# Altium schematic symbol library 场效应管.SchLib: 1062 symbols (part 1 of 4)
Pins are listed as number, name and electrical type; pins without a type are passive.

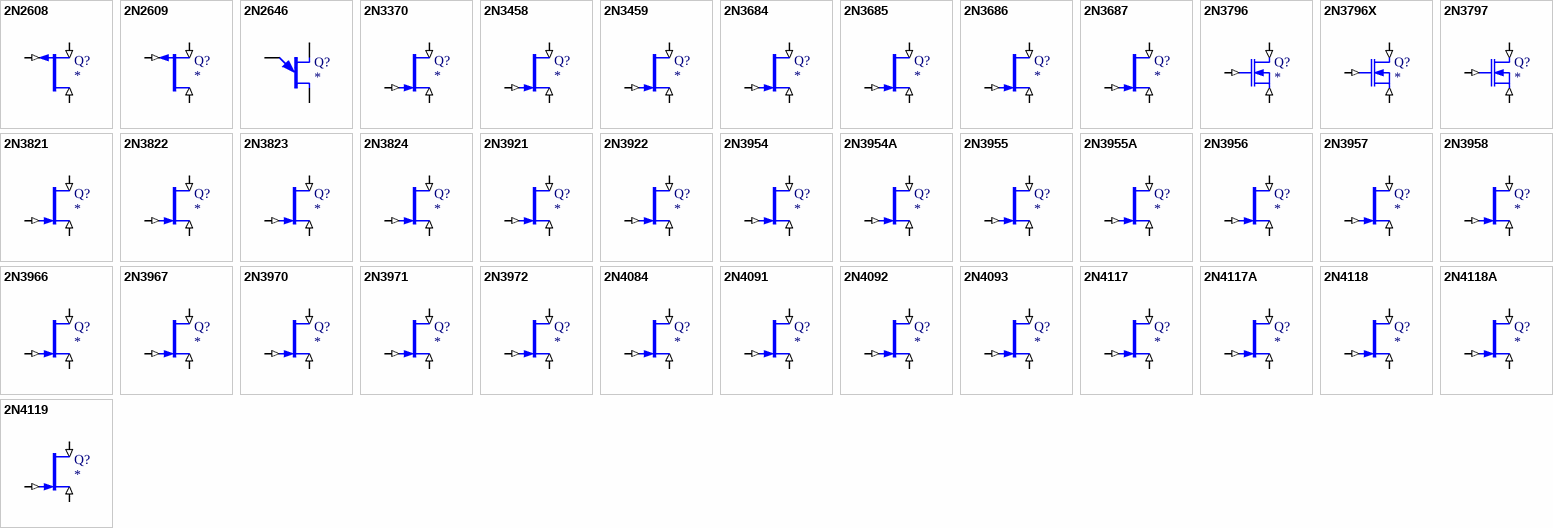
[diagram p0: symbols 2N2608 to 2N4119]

## 2N2608
designator Q?
P-Channel JFET
simulation model 2N2608 (PJFET)
pins: 1 D (in), 2 G (in), 3 S (in)
1 alternate drawing of the same symbol

## 2N2609
designator Q?
P-Channel JFET
simulation model 2N2609 (PJFET)
pins: 1 D (in), 2 G (in), 3 S (in)
1 alternate drawing of the same symbol

## 2N2646
designator Q?
Unijunction Transistor
simulation model 2N2646 (SUBCKT)
pins: 1 B2, 2 E, 3 B1
1 alternate drawing of the same symbol

## 2N3370
designator Q?
N-Channel JFET
simulation model 2N3370 (NJFET)
pins: 1 D (in), 2 G (in), 3 S (in)
1 alternate drawing of the same symbol

## 2N3458
designator Q?
N-Channel JFET
simulation model 2N3458 (NJFET)
pins: 1 D (in), 2 G (in), 3 S (in)
1 alternate drawing of the same symbol

## 2N3459
designator Q?
N-Channel JFET
simulation model 2N3459 (NJFET)
pins: 1 D (in), 2 G (in), 3 S (in)
1 alternate drawing of the same symbol

## 2N3684
designator Q?
N-Channel JFET
simulation model 2N3684 (NJFET)
pins: 1 D (in), 2 G (in), 3 S (in)
1 alternate drawing of the same symbol

## 2N3685
designator Q?
N-Channel JFET
simulation model 2N3685 (NJFET)
pins: 1 D (in), 2 G (in), 3 S (in)
1 alternate drawing of the same symbol

## 2N3686
designator Q?
N-Channel JFET
simulation model 2N3686 (NJFET)
pins: 1 D (in), 2 G (in), 3 S (in)
1 alternate drawing of the same symbol

## 2N3687
designator Q?
N-Channel JFET
simulation model 2N3687 (NJFET)
pins: 1 D (in), 2 G (in), 3 S (in)
1 alternate drawing of the same symbol

## 2N3796
designator Q?
N-Channel MOSFET
simulation model 2N3796 (NEMOS)
pins: 1 D (in), 2 G (in), 3 S (in)
1 alternate drawing of the same symbol

## 2N3796X
designator Q?
N-Channel MOSFET
simulation model 2N3796X (NEMOS)
pins: 1 D (in), 2 G (in), 3 S (in)
1 alternate drawing of the same symbol

## 2N3797
designator Q?
N-Channel MOSFET
simulation model 2N3797 (NEMOS)
pins: 1 D (in), 2 G (in), 3 S (in)
1 alternate drawing of the same symbol

## 2N3821
designator Q?
N-Channel JFET
simulation model 2N3821 (NJFET)
pins: 1 D (in), 2 G (in), 3 S (in)
1 alternate drawing of the same symbol

## 2N3822
designator Q?
N-Channel JFET
simulation model 2N3822 (NJFET)
pins: 1 D (in), 2 G (in), 3 S (in)
1 alternate drawing of the same symbol

## 2N3823
designator Q?
N-Channel JFET
simulation model 2N3823 (NJFET)
pins: 1 D (in), 2 G (in), 3 S (in)
1 alternate drawing of the same symbol

## 2N3824
designator Q?
N-Channel JFET
simulation model 2N3824 (NJFET)
pins: 1 D (in), 2 G (in), 3 S (in)
1 alternate drawing of the same symbol

## 2N3921
designator Q?
N-Channel JFET
simulation model 2N3921 (NJFET)
pins: 1 D (in), 2 G (in), 3 S (in)
1 alternate drawing of the same symbol

## 2N3922
designator Q?
N-Channel JFET
simulation model 2N3922 (NJFET)
pins: 1 D (in), 2 G (in), 3 S (in)
1 alternate drawing of the same symbol

## 2N3954
designator Q?
N-Channel JFET
simulation model 2N3954 (NJFET)
pins: 1 D (in), 2 G (in), 3 S (in)
1 alternate drawing of the same symbol

## 2N3954A
designator Q?
N-Channel JFET
simulation model 2N3954A (NJFET)
pins: 1 D (in), 2 G (in), 3 S (in)
1 alternate drawing of the same symbol

## 2N3955
designator Q?
N-Channel JFET
simulation model 2N3955 (NJFET)
pins: 1 D (in), 2 G (in), 3 S (in)
1 alternate drawing of the same symbol

## 2N3955A
designator Q?
N-Channel JFET
simulation model 2N3955A (NJFET)
pins: 1 D (in), 2 G (in), 3 S (in)
1 alternate drawing of the same symbol

## 2N3956
designator Q?
N-Channel JFET
simulation model 2N3956 (NJFET)
pins: 1 D (in), 2 G (in), 3 S (in)
1 alternate drawing of the same symbol

## 2N3957
designator Q?
N-Channel JFET
simulation model 2N3957 (NJFET)
pins: 1 D (in), 2 G (in), 3 S (in)
1 alternate drawing of the same symbol

## 2N3958
designator Q?
N-Channel JFET
simulation model 2N3958 (NJFET)
pins: 1 D (in), 2 G (in), 3 S (in)
1 alternate drawing of the same symbol

## 2N3966
designator Q?
N-Channel JFET
simulation model 2N3966 (NJFET)
pins: 1 D (in), 2 G (in), 3 S (in)
1 alternate drawing of the same symbol

## 2N3967
designator Q?
N-Channel JFET
simulation model 2N3967 (NJFET)
pins: 1 D (in), 2 G (in), 3 S (in)
1 alternate drawing of the same symbol

## 2N3970
designator Q?
N-Channel JFET
simulation model 2N3970 (NJFET)
pins: 1 D (in), 2 G (in), 3 S (in)
1 alternate drawing of the same symbol

## 2N3971
designator Q?
N-Channel JFET
simulation model 2N3971 (NJFET)
pins: 1 D (in), 2 G (in), 3 S (in)
1 alternate drawing of the same symbol

## 2N3972
designator Q?
N-Channel JFET
simulation model 2N3972 (NJFET)
pins: 1 D (in), 2 G (in), 3 S (in)
1 alternate drawing of the same symbol

## 2N4084
designator Q?
N-Channel JFET
simulation model 2N4084 (NJFET)
pins: 1 D (in), 2 G (in), 3 S (in)
1 alternate drawing of the same symbol

## 2N4091
designator Q?
N-Channel JFET
simulation model 2N4091 (NJFET)
pins: 1 D (in), 2 G (in), 3 S (in)
1 alternate drawing of the same symbol

## 2N4092
designator Q?
N-Channel JFET
simulation model 2N4092 (NJFET)
pins: 1 D (in), 2 G (in), 3 S (in)
1 alternate drawing of the same symbol

## 2N4093
designator Q?
N-Channel JFET
simulation model 2N4093 (NJFET)
pins: 1 D (in), 2 G (in), 3 S (in)
1 alternate drawing of the same symbol

## 2N4117
designator Q?
N-Channel JFET
simulation model 2N4117 (NJFET)
pins: 1 D (in), 2 G (in), 3 S (in)
1 alternate drawing of the same symbol

## 2N4117A
designator Q?
N-Channel JFET
simulation model 2N4117A (NJFET)
pins: 1 D (in), 2 G (in), 3 S (in)
1 alternate drawing of the same symbol

## 2N4118
designator Q?
N-Channel JFET
simulation model 2N4118 (NJFET)
pins: 1 D (in), 2 G (in), 3 S (in)
1 alternate drawing of the same symbol

## 2N4118A
designator Q?
N-Channel JFET
simulation model 2N4118A (NJFET)
pins: 1 D (in), 2 G (in), 3 S (in)
1 alternate drawing of the same symbol

## 2N4119
designator Q?
N-Channel JFET
simulation model 2N4119 (NJFET)
pins: 1 D (in), 2 G (in), 3 S (in)
1 alternate drawing of the same symbol

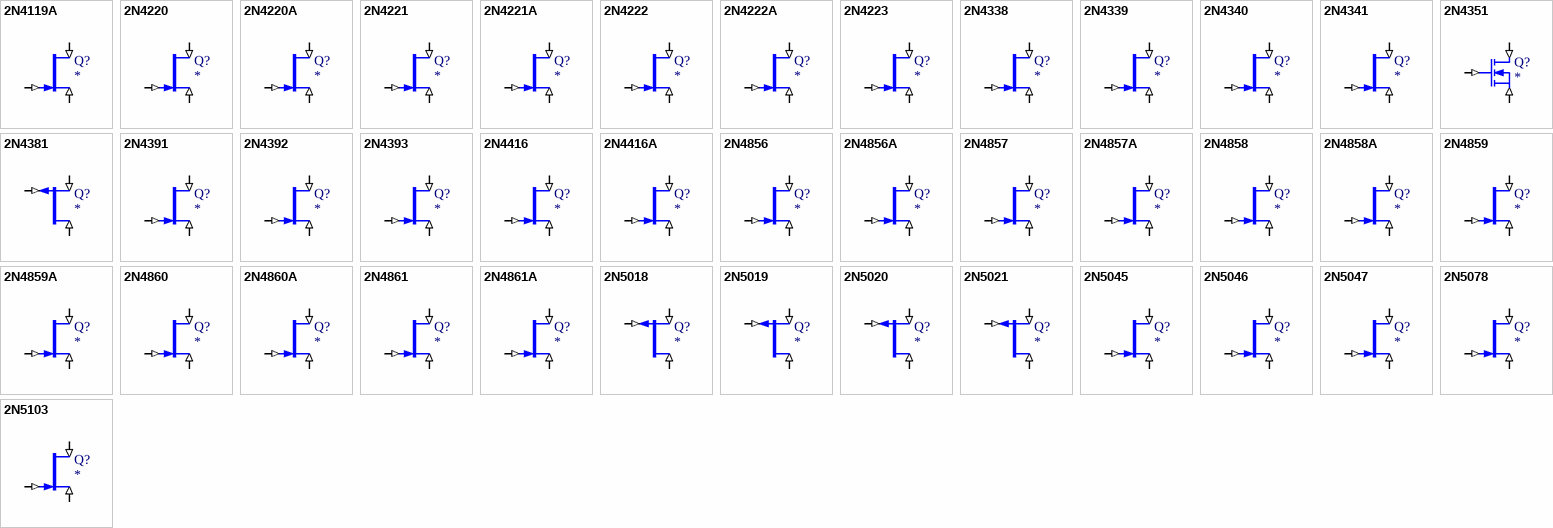
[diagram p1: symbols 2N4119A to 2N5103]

## 2N4119A
designator Q?
N-Channel JFET
simulation model 2N4119A (NJFET)
pins: 1 D (in), 2 G (in), 3 S (in)
1 alternate drawing of the same symbol

## 2N4220
designator Q?
N-Channel JFET
simulation model 2N4220 (NJFET)
pins: 1 D (in), 2 G (in), 3 S (in)
1 alternate drawing of the same symbol

## 2N4220A
designator Q?
N-Channel JFET
simulation model 2N4220A (NJFET)
pins: 1 D (in), 2 G (in), 3 S (in)
1 alternate drawing of the same symbol

## 2N4221
designator Q?
N-Channel JFET
simulation model 2N4221 (NJFET)
pins: 1 D (in), 2 G (in), 3 S (in)
1 alternate drawing of the same symbol

## 2N4221A
designator Q?
N-Channel JFET
simulation model 2N4221A (NJFET)
pins: 1 D (in), 2 G (in), 3 S (in)
1 alternate drawing of the same symbol

## 2N4222
designator Q?
N-Channel JFET
simulation model 2N4222 (NJFET)
pins: 1 D (in), 2 G (in), 3 S (in)
1 alternate drawing of the same symbol

## 2N4222A
designator Q?
N-Channel JFET
simulation model 2N4222A (NJFET)
pins: 1 D (in), 2 G (in), 3 S (in)
1 alternate drawing of the same symbol

## 2N4223
designator Q?
N-Channel JFET
simulation model 2N4223 (NJFET)
pins: 1 D (in), 2 G (in), 3 S (in)
1 alternate drawing of the same symbol

## 2N4338
designator Q?
N-Channel JFET
simulation model 2N4338 (NJFET)
pins: 1 D (in), 2 G (in), 3 S (in)
1 alternate drawing of the same symbol

## 2N4339
designator Q?
N-Channel JFET
simulation model 2N4339 (NJFET)
pins: 1 D (in), 2 G (in), 3 S (in)
1 alternate drawing of the same symbol

## 2N4340
designator Q?
N-Channel JFET
simulation model 2N4340 (NJFET)
pins: 1 D (in), 2 G (in), 3 S (in)
1 alternate drawing of the same symbol

## 2N4341
designator Q?
N-Channel JFET
simulation model 2N4341 (NJFET)
pins: 1 D (in), 2 G (in), 3 S (in)
1 alternate drawing of the same symbol

## 2N4351
designator Q?
N-Channel MOSFET
simulation model 2N4351 (NEMOS)
pins: 1 D (in), 2 G (in), 3 S (in)
1 alternate drawing of the same symbol

## 2N4381
designator Q?
P-Channel JFET
simulation model 2N4381 (PJFET)
pins: 1 D (in), 2 G (in), 3 S (in)
1 alternate drawing of the same symbol

## 2N4391
designator Q?
N-Channel JFET
simulation model 2N4391 (NJFET)
pins: 1 D (in), 2 G (in), 3 S (in)
1 alternate drawing of the same symbol

## 2N4392
designator Q?
N-Channel JFET
simulation model 2N4392 (NJFET)
pins: 1 D (in), 2 G (in), 3 S (in)
1 alternate drawing of the same symbol

## 2N4393
designator Q?
N-Channel JFET
simulation model 2N4393 (NJFET)
pins: 1 D (in), 2 G (in), 3 S (in)
1 alternate drawing of the same symbol

## 2N4416
designator Q?
N-Channel JFET
simulation model 2N4416 (NJFET)
pins: 1 D (in), 2 G (in), 3 S (in)
1 alternate drawing of the same symbol

## 2N4416A
designator Q?
N-Channel JFET
simulation model 2N4416A (NJFET)
pins: 1 D (in), 2 G (in), 3 S (in)
1 alternate drawing of the same symbol

## 2N4856
designator Q?
N-Channel JFET
simulation model 2N4856 (NJFET)
pins: 1 D (in), 2 G (in), 3 S (in)
1 alternate drawing of the same symbol

## 2N4856A
designator Q?
N-Channel JFET
simulation model 2N4856A (NJFET)
pins: 1 D (in), 2 G (in), 3 S (in)
1 alternate drawing of the same symbol

## 2N4857
designator Q?
N-Channel JFET
simulation model 2N4857 (NJFET)
pins: 1 D (in), 2 G (in), 3 S (in)
1 alternate drawing of the same symbol

## 2N4857A
designator Q?
N-Channel JFET
simulation model 2N4857A (NJFET)
pins: 1 D (in), 2 G (in), 3 S (in)
1 alternate drawing of the same symbol

## 2N4858
designator Q?
N-Channel JFET
simulation model 2N4858 (NJFET)
pins: 1 D (in), 2 G (in), 3 S (in)
1 alternate drawing of the same symbol

## 2N4858A
designator Q?
N-Channel JFET
simulation model 2N4858A (NJFET)
pins: 1 D (in), 2 G (in), 3 S (in)
1 alternate drawing of the same symbol

## 2N4859
designator Q?
N-Channel JFET
simulation model 2N4859 (NJFET)
pins: 1 D (in), 2 G (in), 3 S (in)
1 alternate drawing of the same symbol

## 2N4859A
designator Q?
N-Channel JFET
simulation model 2N4859A (NJFET)
pins: 1 D (in), 2 G (in), 3 S (in)
1 alternate drawing of the same symbol

## 2N4860
designator Q?
N-Channel JFET
simulation model 2N4860 (NJFET)
pins: 1 D (in), 2 G (in), 3 S (in)
1 alternate drawing of the same symbol

## 2N4860A
designator Q?
N-Channel JFET
simulation model 2N4860A (NJFET)
pins: 1 D (in), 2 G (in), 3 S (in)
1 alternate drawing of the same symbol

## 2N4861
designator Q?
N-Channel JFET
simulation model 2N4861 (NJFET)
pins: 1 D (in), 2 G (in), 3 S (in)
1 alternate drawing of the same symbol

## 2N4861A
designator Q?
N-Channel JFET
simulation model 2N4861A (NJFET)
pins: 1 D (in), 2 G (in), 3 S (in)
1 alternate drawing of the same symbol

## 2N5018
designator Q?
P-Channel JFET
simulation model 2N5018 (PJFET)
pins: 1 D (in), 2 G (in), 3 S (in)
1 alternate drawing of the same symbol

## 2N5019
designator Q?
P-Channel JFET
simulation model 2N5019 (PJFET)
pins: 1 D (in), 2 G (in), 3 S (in)
1 alternate drawing of the same symbol

## 2N5020
designator Q?
P-Channel JFET
simulation model 2N5020 (PJFET)
pins: 1 D (in), 2 G (in), 3 S (in)
1 alternate drawing of the same symbol

## 2N5021
designator Q?
P-Channel JFET
simulation model 2N5021 (PJFET)
pins: 1 D (in), 2 G (in), 3 S (in)
1 alternate drawing of the same symbol

## 2N5045
designator Q?
N-Channel JFET
simulation model 2N5045 (NJFET)
pins: 1 D (in), 2 G (in), 3 S (in)
1 alternate drawing of the same symbol

## 2N5046
designator Q?
N-Channel JFET
simulation model 2N5046 (NJFET)
pins: 1 D (in), 2 G (in), 3 S (in)
1 alternate drawing of the same symbol

## 2N5047
designator Q?
N-Channel JFET
simulation model 2N5047 (NJFET)
pins: 1 D (in), 2 G (in), 3 S (in)
1 alternate drawing of the same symbol

## 2N5078
designator Q?
N-Channel JFET
simulation model 2N5078 (NJFET)
pins: 1 D (in), 2 G (in), 3 S (in)
1 alternate drawing of the same symbol

## 2N5103
designator Q?
N-Channel JFET
simulation model 2N5103 (NJFET)
pins: 1 D (in), 2 G (in), 3 S (in)
1 alternate drawing of the same symbol

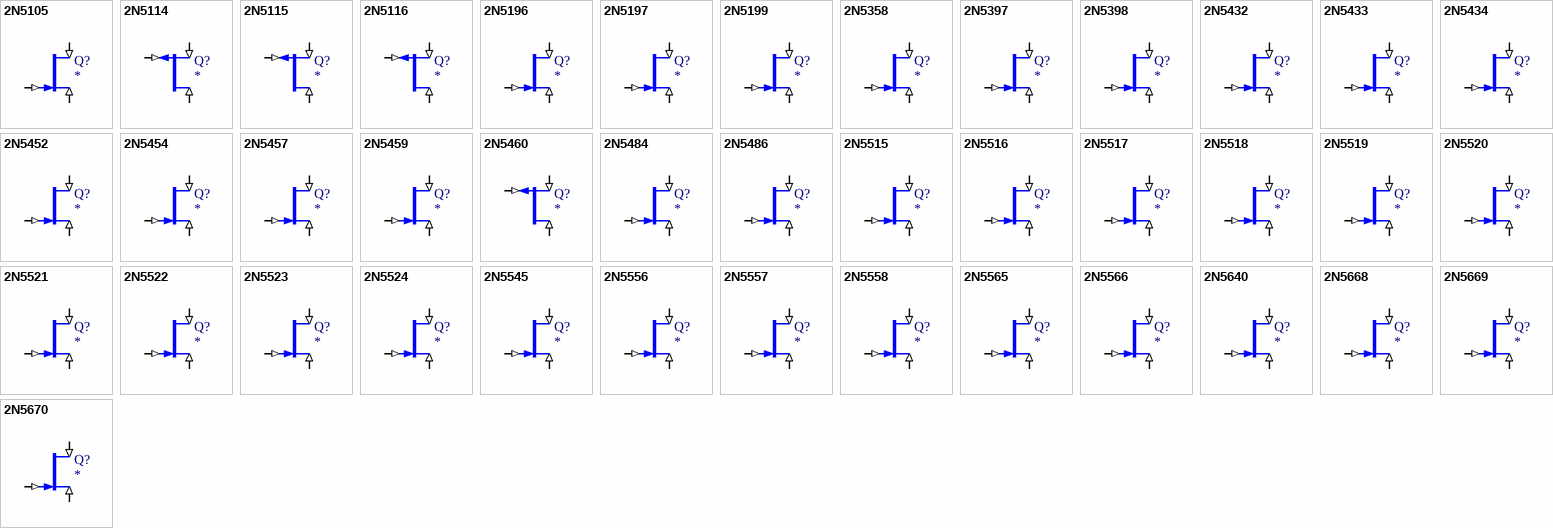
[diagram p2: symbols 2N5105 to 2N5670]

## 2N5105
designator Q?
N-Channel JFET
simulation model 2N5105 (NJFET)
pins: 1 D (in), 2 G (in), 3 S (in)
1 alternate drawing of the same symbol

## 2N5114
designator Q?
P-Channel JFET
simulation model 2N5114 (PJFET)
pins: 1 D (in), 2 G (in), 3 S (in)
1 alternate drawing of the same symbol

## 2N5115
designator Q?
P-Channel JFET
simulation model 2N5115 (PJFET)
pins: 1 D (in), 2 G (in), 3 S (in)
1 alternate drawing of the same symbol

## 2N5116
designator Q?
P-Channel JFET
simulation model 2N5116 (PJFET)
pins: 1 D (in), 2 G (in), 3 S (in)
1 alternate drawing of the same symbol

## 2N5196
designator Q?
N-Channel JFET
simulation model 2N5196 (NJFET)
pins: 1 D (in), 2 G (in), 3 S (in)
1 alternate drawing of the same symbol

## 2N5197
designator Q?
N-Channel JFET
simulation model 2N5197 (NJFET)
pins: 1 D (in), 2 G (in), 3 S (in)
1 alternate drawing of the same symbol

## 2N5199
designator Q?
N-Channel JFET
simulation model 2N5199 (NJFET)
pins: 1 D (in), 2 G (in), 3 S (in)
1 alternate drawing of the same symbol

## 2N5358
designator Q?
N-Channel JFET
simulation model 2N5358 (NJFET)
pins: 1 D (in), 2 G (in), 3 S (in)
1 alternate drawing of the same symbol

## 2N5397
designator Q?
N-Channel JFET
simulation model 2N5397 (NJFET)
pins: 1 D (in), 2 G (in), 3 S (in)
1 alternate drawing of the same symbol

## 2N5398
designator Q?
N-Channel JFET
simulation model 2N5398 (NJFET)
pins: 1 D (in), 2 G (in), 3 S (in)
1 alternate drawing of the same symbol

## 2N5432
designator Q?
N-Channel JFET
simulation model 2N5432 (NJFET)
pins: 1 D (in), 2 G (in), 3 S (in)
1 alternate drawing of the same symbol

## 2N5433
designator Q?
N-Channel JFET
simulation model 2N5433 (NJFET)
pins: 1 D (in), 2 G (in), 3 S (in)
1 alternate drawing of the same symbol

## 2N5434
designator Q?
N-Channel JFET
simulation model 2N5434 (NJFET)
pins: 1 D (in), 2 G (in), 3 S (in)
1 alternate drawing of the same symbol

## 2N5452
designator Q?
N-Channel JFET
simulation model 2N5452 (NJFET)
pins: 1 D (in), 2 G (in), 3 S (in)
1 alternate drawing of the same symbol

## 2N5454
designator Q?
N-Channel JFET
simulation model 2N5454 (NJFET)
pins: 1 D (in), 2 G (in), 3 S (in)
1 alternate drawing of the same symbol

## 2N5457
designator Q?
N-Channel JFET
simulation model 2N5457 (NJFET)
pins: 1 D (in), 2 G (in), 3 S (in)
1 alternate drawing of the same symbol

## 2N5459
designator Q?
N-Channel JFET
simulation model 2N5459 (NJFET)
pins: 1 D (in), 2 G (in), 3 S (in)
1 alternate drawing of the same symbol

## 2N5460
designator Q?
P-Channel JFET
simulation model 2N5460 (PJFET)
pins: 1 D (in), 2 G (in), 3 S (in)
1 alternate drawing of the same symbol

## 2N5484
designator Q?
N-Channel JFET
simulation model 2N5484 (NJFET)
pins: 1 D (in), 2 G (in), 3 S (in)
1 alternate drawing of the same symbol

## 2N5486
designator Q?
N-Channel JFET
simulation model 2N5486 (NJFET)
pins: 1 D (in), 2 G (in), 3 S (in)
1 alternate drawing of the same symbol

## 2N5515
designator Q?
N-Channel JFET
simulation model 2N5515 (NJFET)
pins: 1 D (in), 2 G (in), 3 S (in)
1 alternate drawing of the same symbol

## 2N5516
designator Q?
N-Channel JFET
simulation model 2N5516 (NJFET)
pins: 1 D (in), 2 G (in), 3 S (in)
1 alternate drawing of the same symbol

## 2N5517
designator Q?
N-Channel JFET
simulation model 2N5517 (NJFET)
pins: 1 D (in), 2 G (in), 3 S (in)
1 alternate drawing of the same symbol

## 2N5518
designator Q?
N-Channel JFET
simulation model 2N5518 (NJFET)
pins: 1 D (in), 2 G (in), 3 S (in)
1 alternate drawing of the same symbol

## 2N5519
designator Q?
N-Channel JFET
simulation model 2N5519 (NJFET)
pins: 1 D (in), 2 G (in), 3 S (in)
1 alternate drawing of the same symbol

## 2N5520
designator Q?
N-Channel JFET
simulation model 2N5520 (NJFET)
pins: 1 D (in), 2 G (in), 3 S (in)
1 alternate drawing of the same symbol

## 2N5521
designator Q?
N-Channel JFET
simulation model 2N5521 (NJFET)
pins: 1 D (in), 2 G (in), 3 S (in)
1 alternate drawing of the same symbol

## 2N5522
designator Q?
N-Channel JFET
simulation model 2N5522 (NJFET)
pins: 1 D (in), 2 G (in), 3 S (in)
1 alternate drawing of the same symbol

## 2N5523
designator Q?
N-Channel JFET
simulation model 2N5523 (NJFET)
pins: 1 D (in), 2 G (in), 3 S (in)
1 alternate drawing of the same symbol

## 2N5524
designator Q?
N-Channel JFET
simulation model 2N5524 (NJFET)
pins: 1 D (in), 2 G (in), 3 S (in)
1 alternate drawing of the same symbol

## 2N5545
designator Q?
N-Channel JFET
simulation model 2N5545 (NJFET)
pins: 1 D (in), 2 G (in), 3 S (in)
1 alternate drawing of the same symbol

## 2N5556
designator Q?
N-Channel JFET
simulation model 2N5556 (NJFET)
pins: 1 D (in), 2 G (in), 3 S (in)
1 alternate drawing of the same symbol

## 2N5557
designator Q?
N-Channel JFET
simulation model 2N5557 (NJFET)
pins: 1 D (in), 2 G (in), 3 S (in)
1 alternate drawing of the same symbol

## 2N5558
designator Q?
N-Channel JFET
simulation model 2N5558 (NJFET)
pins: 1 D (in), 2 G (in), 3 S (in)
1 alternate drawing of the same symbol

## 2N5565
designator Q?
N-Channel JFET
simulation model 2N5565 (NJFET)
pins: 1 D (in), 2 G (in), 3 S (in)
1 alternate drawing of the same symbol

## 2N5566
designator Q?
N-Channel JFET
simulation model 2N5566 (NJFET)
pins: 1 D (in), 2 G (in), 3 S (in)
1 alternate drawing of the same symbol

## 2N5640
designator Q?
N-Channel JFET
simulation model 2N5640 (NJFET)
pins: 1 D (in), 2 G (in), 3 S (in)
1 alternate drawing of the same symbol

## 2N5668
designator Q?
N-Channel JFET
simulation model 2N5668 (NJFET)
pins: 1 D (in), 2 G (in), 3 S (in)
1 alternate drawing of the same symbol

## 2N5669
designator Q?
N-Channel JFET
simulation model 2N5669 (NJFET)
pins: 1 D (in), 2 G (in), 3 S (in)
1 alternate drawing of the same symbol

## 2N5670
designator Q?
N-Channel JFET
simulation model 2N5670 (NJFET)
pins: 1 D (in), 2 G (in), 3 S (in)
1 alternate drawing of the same symbol

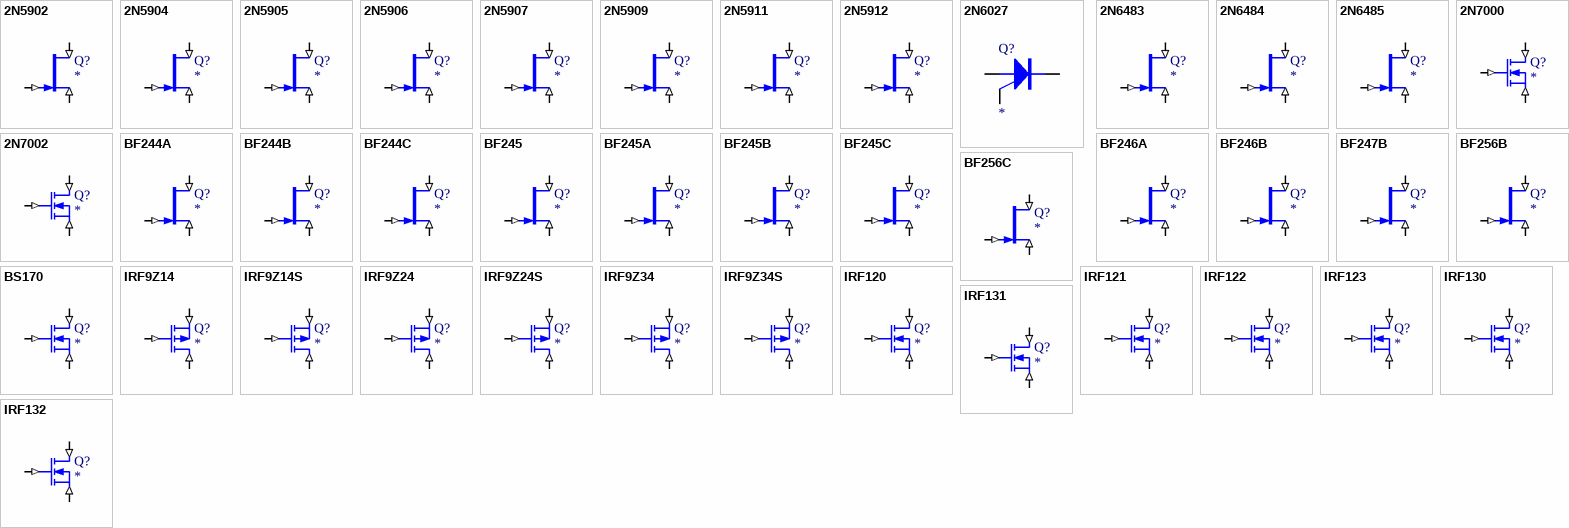
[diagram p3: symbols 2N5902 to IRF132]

## 2N5902
designator Q?
N-Channel JFET
simulation model 2N5902 (NJFET)
pins: 1 D (in), 2 G (in), 3 S (in)
1 alternate drawing of the same symbol

## 2N5904
designator Q?
N-Channel JFET
simulation model 2N5904 (NJFET)
pins: 1 D (in), 2 G (in), 3 S (in)
1 alternate drawing of the same symbol

## 2N5905
designator Q?
N-Channel JFET
simulation model 2N5905 (NJFET)
pins: 1 D (in), 2 G (in), 3 S (in)
1 alternate drawing of the same symbol

## 2N5906
designator Q?
N-Channel JFET
simulation model 2N5906 (NJFET)
pins: 1 D (in), 2 G (in), 3 S (in)
1 alternate drawing of the same symbol

## 2N5907
designator Q?
N-Channel JFET
simulation model 2N5907 (NJFET)
pins: 1 D (in), 2 G (in), 3 S (in)
1 alternate drawing of the same symbol

## 2N5909
designator Q?
N-Channel JFET
simulation model 2N5909 (NJFET)
pins: 1 D (in), 2 G (in), 3 S (in)
1 alternate drawing of the same symbol

## 2N5911
designator Q?
N-Channel JFET
simulation model 2N5911 (NJFET)
pins: 1 D (in), 2 G (in), 3 S (in)
1 alternate drawing of the same symbol

## 2N5912
designator Q?
N-Channel JFET
simulation model 2N5912 (NJFET)
pins: 1 D (in), 2 G (in), 3 S (in)
1 alternate drawing of the same symbol

## 2N6027
designator Q?
Programmable Unijunction Transistor
simulation model 2N6027 (SUBCKT)
pins: 1 A, 2 G, 3 K
1 alternate drawing of the same symbol

## 2N6483
designator Q?
N-Channel JFET
simulation model 2N6483 (NJFET)
pins: 1 D (in), 2 G (in), 3 S (in)
1 alternate drawing of the same symbol

## 2N6484
designator Q?
N-Channel JFET
simulation model 2N6484 (NJFET)
pins: 1 D (in), 2 G (in), 3 S (in)
1 alternate drawing of the same symbol

## 2N6485
designator Q?
N-Channel JFET
simulation model 2N6485 (NJFET)
pins: 1 D (in), 2 G (in), 3 S (in)
1 alternate drawing of the same symbol

## 2N7000
designator Q?
N-Channel MOSFET
simulation model 2N7000 (SUBCKT)
pins: 1 D (in), 2 G (in), 3 S (in)
1 alternate drawing of the same symbol

## 2N7002
designator Q?
N-Channel MOSFET
simulation model 2N7002 (SUBCKT)
pins: 1 D (in), 2 G (in), 3 S (in)
1 alternate drawing of the same symbol

## BF244A
designator Q?
N-Channel JFET
simulation model BF244A (NJFET)
pins: 1 D (in), 2 G (in), 3 S (in)
1 alternate drawing of the same symbol

## BF244B
designator Q?
N-Channel JFET
simulation model BF244B (NJFET)
pins: 1 D (in), 2 G (in), 3 S (in)
1 alternate drawing of the same symbol

## BF244C
designator Q?
N-Channel JFET
simulation model BF244C (NJFET)
pins: 1 D (in), 2 G (in), 3 S (in)
1 alternate drawing of the same symbol

## BF245
designator Q?
N-Channel JFET
simulation model BF245 (NJFET)
pins: 1 D (in), 2 G (in), 3 S (in)
1 alternate drawing of the same symbol

## BF245A
designator Q?
N-Channel JFET
simulation model BF245A (NJFET)
pins: 1 D (in), 2 G (in), 3 S (in)
1 alternate drawing of the same symbol

## BF245B
designator Q?
N-Channel JFET
simulation model BF245B (NJFET)
pins: 1 D (in), 2 G (in), 3 S (in)
1 alternate drawing of the same symbol

## BF245C
designator Q?
N-Channel JFET
simulation model BF245C (NJFET)
pins: 1 D (in), 2 G (in), 3 S (in)
1 alternate drawing of the same symbol

## BF246A
designator Q?
N-Channel JFET
simulation model BF246A (NJFET)
pins: 1 D (in), 2 G (in), 3 S (in)
1 alternate drawing of the same symbol

## BF246B
designator Q?
N-Channel JFET
simulation model BF246B (NJFET)
pins: 1 D (in), 2 G (in), 3 S (in)
1 alternate drawing of the same symbol

## BF247B
designator Q?
N-Channel JFET
simulation model BF247B (NJFET)
pins: 1 D (in), 2 G (in), 3 S (in)
1 alternate drawing of the same symbol

## BF256B
designator Q?
N-Channel JFET
simulation model BF256B (NJFET)
pins: 1 D (in), 2 G (in), 3 S (in)
1 alternate drawing of the same symbol

## BF256C
designator Q?
N-Channel JFET
simulation model BF256C (NJFET)
pins: 1 D (in), 2 G (in), 3 S (in)
1 alternate drawing of the same symbol

## BS170
designator Q?
N-Channel MOSFET
simulation model BS170 (SUBCKT)
pins: 1 D (in), 2 G (in), 3 S (in)
1 alternate drawing of the same symbol

## IRF9Z14
designator Q?
P-Channel MOSFET
simulation model IRF9Z14 (SUBCKT)
pins: 1 D (in), 2 G (in), 3 S (in)
1 alternate drawing of the same symbol

## IRF9Z14S
designator Q?
P-Channel MOSFET
simulation model IRF9Z14S (SUBCKT)
pins: 1 D (in), 2 G (in), 3 S (in)
1 alternate drawing of the same symbol

## IRF9Z24
designator Q?
P-Channel MOSFET
simulation model IRF9Z24 (SUBCKT)
pins: 1 D (in), 2 G (in), 3 S (in)
1 alternate drawing of the same symbol

## IRF9Z24S
designator Q?
P-Channel MOSFET
simulation model IRF9Z24S (SUBCKT)
pins: 1 D (in), 2 G (in), 3 S (in)
1 alternate drawing of the same symbol

## IRF9Z34
designator Q?
P-Channel MOSFET
simulation model IRF9Z34 (SUBCKT)
pins: 1 D (in), 2 G (in), 3 S (in)
1 alternate drawing of the same symbol

## IRF9Z34S
designator Q?
P-Channel MOSFET
simulation model IRF9Z34S (SUBCKT)
pins: 1 D (in), 2 G (in), 3 S (in)
1 alternate drawing of the same symbol

## IRF120
designator Q?
N-Channel MOSFET
simulation model IRF120 (SUBCKT)
pins: 1 D (in), 2 G (in), 3 S (in)
1 alternate drawing of the same symbol

## IRF121
designator Q?
N-Channel MOSFET
simulation model IRF121 (SUBCKT)
pins: 1 D (in), 2 G (in), 3 S (in)
1 alternate drawing of the same symbol

## IRF122
designator Q?
N-Channel MOSFET
simulation model IRF122 (SUBCKT)
pins: 1 D (in), 2 G (in), 3 S (in)
1 alternate drawing of the same symbol

## IRF123
designator Q?
N-Channel MOSFET
simulation model IRF123 (SUBCKT)
pins: 1 D (in), 2 G (in), 3 S (in)
1 alternate drawing of the same symbol

## IRF130
designator Q?
N-Channel MOSFET
simulation model IRF130 (SUBCKT)
pins: 1 D (in), 2 G (in), 3 S (in)
1 alternate drawing of the same symbol

## IRF131
designator Q?
N-Channel MOSFET
simulation model IRF131 (SUBCKT)
pins: 1 D (in), 2 G (in), 3 S (in)
1 alternate drawing of the same symbol

## IRF132
designator Q?
N-Channel MOSFET
simulation model IRF132 (SUBCKT)
pins: 1 D (in), 2 G (in), 3 S (in)
1 alternate drawing of the same symbol

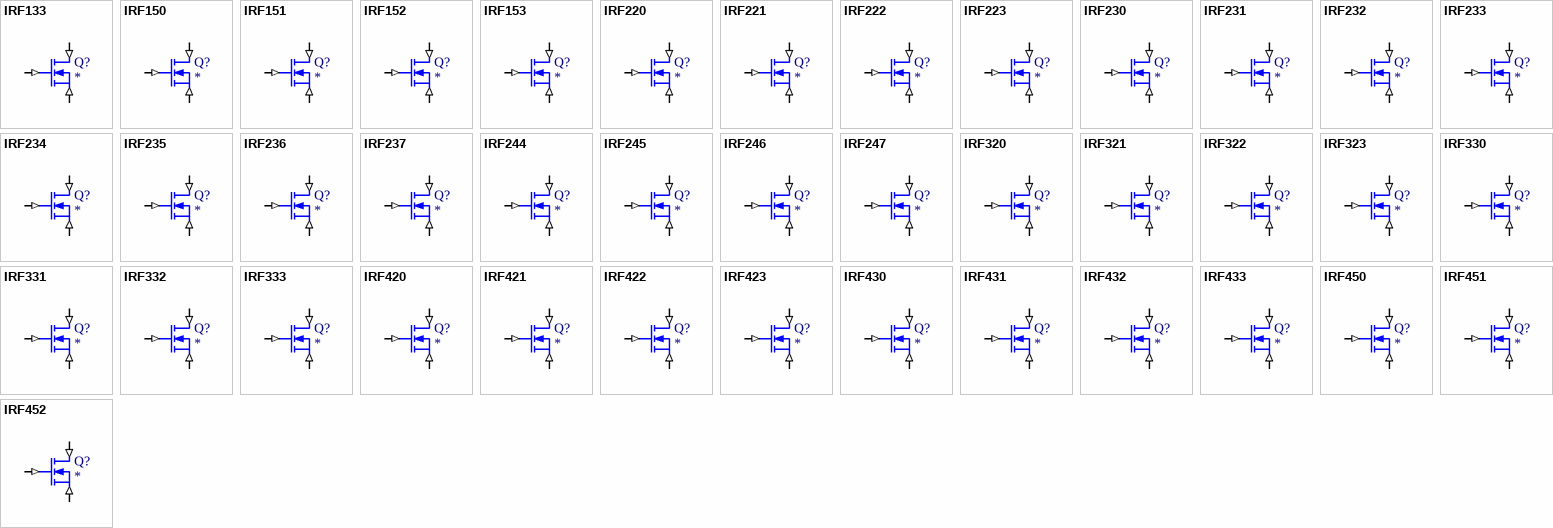
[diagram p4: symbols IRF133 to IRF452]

## IRF133
designator Q?
N-Channel MOSFET
simulation model IRF133 (SUBCKT)
pins: 1 D (in), 2 G (in), 3 S (in)
1 alternate drawing of the same symbol

## IRF150
designator Q?
N-Channel MOSFET
simulation model IRF150 (SUBCKT)
pins: 1 D (in), 2 G (in), 3 S (in)
1 alternate drawing of the same symbol

## IRF151
designator Q?
N-Channel MOSFET
simulation model IRF151 (SUBCKT)
pins: 1 D (in), 2 G (in), 3 S (in)
1 alternate drawing of the same symbol

## IRF152
designator Q?
N-Channel MOSFET
simulation model IRF152 (SUBCKT)
pins: 1 D (in), 2 G (in), 3 S (in)
1 alternate drawing of the same symbol

## IRF153
designator Q?
N-Channel MOSFET
simulation model IRF153 (SUBCKT)
pins: 1 D (in), 2 G (in), 3 S (in)
1 alternate drawing of the same symbol

## IRF220
designator Q?
N-Channel MOSFET
simulation model IRF220 (SUBCKT)
pins: 1 D (in), 2 G (in), 3 S (in)
1 alternate drawing of the same symbol

## IRF221
designator Q?
N-Channel MOSFET
simulation model IRF221 (SUBCKT)
pins: 1 D (in), 2 G (in), 3 S (in)
1 alternate drawing of the same symbol

## IRF222
designator Q?
N-Channel MOSFET
simulation model IRF222 (SUBCKT)
pins: 1 D (in), 2 G (in), 3 S (in)
1 alternate drawing of the same symbol

## IRF223
designator Q?
N-Channel MOSFET
simulation model IRF223 (SUBCKT)
pins: 1 D (in), 2 G (in), 3 S (in)
1 alternate drawing of the same symbol

## IRF230
designator Q?
N-Channel MOSFET
simulation model IRF230 (SUBCKT)
pins: 1 D (in), 2 G (in), 3 S (in)
1 alternate drawing of the same symbol

## IRF231
designator Q?
N-Channel MOSFET
simulation model IRF231 (SUBCKT)
pins: 1 D (in), 2 G (in), 3 S (in)
1 alternate drawing of the same symbol

## IRF232
designator Q?
N-Channel MOSFET
simulation model IRF232 (SUBCKT)
pins: 1 D (in), 2 G (in), 3 S (in)
1 alternate drawing of the same symbol

## IRF233
designator Q?
N-Channel MOSFET
simulation model IRF233 (SUBCKT)
pins: 1 D (in), 2 G (in), 3 S (in)
1 alternate drawing of the same symbol

## IRF234
designator Q?
N-Channel MOSFET
simulation model IRF234 (SUBCKT)
pins: 1 D (in), 2 G (in), 3 S (in)
1 alternate drawing of the same symbol

## IRF235
designator Q?
N-Channel MOSFET
simulation model IRF235 (SUBCKT)
pins: 1 D (in), 2 G (in), 3 S (in)
1 alternate drawing of the same symbol

## IRF236
designator Q?
N-Channel MOSFET
simulation model IRF236 (SUBCKT)
pins: 1 D (in), 2 G (in), 3 S (in)
1 alternate drawing of the same symbol

## IRF237
designator Q?
N-Channel MOSFET
simulation model IRF237 (SUBCKT)
pins: 1 D (in), 2 G (in), 3 S (in)
1 alternate drawing of the same symbol

## IRF244
designator Q?
N-Channel MOSFET
simulation model IRF244 (SUBCKT)
pins: 1 D (in), 2 G (in), 3 S (in)
1 alternate drawing of the same symbol

## IRF245
designator Q?
N-Channel MOSFET
simulation model IRF245 (SUBCKT)
pins: 1 D (in), 2 G (in), 3 S (in)
1 alternate drawing of the same symbol

## IRF246
designator Q?
N-Channel MOSFET
simulation model IRF246 (SUBCKT)
pins: 1 D (in), 2 G (in), 3 S (in)
1 alternate drawing of the same symbol

## IRF247
designator Q?
N-Channel MOSFET
simulation model IRF247 (SUBCKT)
pins: 1 D (in), 2 G (in), 3 S (in)
1 alternate drawing of the same symbol

## IRF320
designator Q?
N-Channel MOSFET
simulation model IRF320 (SUBCKT)
pins: 1 D (in), 2 G (in), 3 S (in)
1 alternate drawing of the same symbol

## IRF321
designator Q?
N-Channel MOSFET
simulation model IRF321 (SUBCKT)
pins: 1 D (in), 2 G (in), 3 S (in)
1 alternate drawing of the same symbol

## IRF322
designator Q?
N-Channel MOSFET
simulation model IRF322 (SUBCKT)
pins: 1 D (in), 2 G (in), 3 S (in)
1 alternate drawing of the same symbol

## IRF323
designator Q?
N-Channel MOSFET
simulation model IRF323 (SUBCKT)
pins: 1 D (in), 2 G (in), 3 S (in)
1 alternate drawing of the same symbol

## IRF330
designator Q?
N-Channel MOSFET
simulation model IRF330 (SUBCKT)
pins: 1 D (in), 2 G (in), 3 S (in)
1 alternate drawing of the same symbol

## IRF331
designator Q?
N-Channel MOSFET
simulation model IRF331 (SUBCKT)
pins: 1 D (in), 2 G (in), 3 S (in)
1 alternate drawing of the same symbol

## IRF332
designator Q?
N-Channel MOSFET
simulation model IRF332 (SUBCKT)
pins: 1 D (in), 2 G (in), 3 S (in)
1 alternate drawing of the same symbol

## IRF333
designator Q?
N-Channel MOSFET
simulation model IRF333 (SUBCKT)
pins: 1 D (in), 2 G (in), 3 S (in)
1 alternate drawing of the same symbol

## IRF420
designator Q?
N-Channel MOSFET
simulation model IRF420 (SUBCKT)
pins: 1 D (in), 2 G (in), 3 S (in)
1 alternate drawing of the same symbol

## IRF421
designator Q?
N-Channel MOSFET
simulation model IRF421 (SUBCKT)
pins: 1 D (in), 2 G (in), 3 S (in)
1 alternate drawing of the same symbol

## IRF422
designator Q?
N-Channel MOSFET
simulation model IRF422 (SUBCKT)
pins: 1 D (in), 2 G (in), 3 S (in)
1 alternate drawing of the same symbol

## IRF423
designator Q?
N-Channel MOSFET
simulation model IRF423 (SUBCKT)
pins: 1 D (in), 2 G (in), 3 S (in)
1 alternate drawing of the same symbol

## IRF430
designator Q?
N-Channel MOSFET
simulation model IRF430 (SUBCKT)
pins: 1 D (in), 2 G (in), 3 S (in)
1 alternate drawing of the same symbol

## IRF431
designator Q?
N-Channel MOSFET
simulation model IRF431 (SUBCKT)
pins: 1 D (in), 2 G (in), 3 S (in)
1 alternate drawing of the same symbol

## IRF432
designator Q?
N-Channel MOSFET
simulation model IRF432 (SUBCKT)
pins: 1 D (in), 2 G (in), 3 S (in)
1 alternate drawing of the same symbol

## IRF433
designator Q?
N-Channel MOSFET
simulation model IRF433 (SUBCKT)
pins: 1 D (in), 2 G (in), 3 S (in)
1 alternate drawing of the same symbol

## IRF450
designator Q?
N-Channel MOSFET
simulation model IRF450 (SUBCKT)
pins: 1 D (in), 2 G (in), 3 S (in)
1 alternate drawing of the same symbol

## IRF451
designator Q?
N-Channel MOSFET
simulation model IRF451 (SUBCKT)
pins: 1 D (in), 2 G (in), 3 S (in)
1 alternate drawing of the same symbol

## IRF452
designator Q?
N-Channel MOSFET
simulation model IRF452 (SUBCKT)
pins: 1 D (in), 2 G (in), 3 S (in)
1 alternate drawing of the same symbol

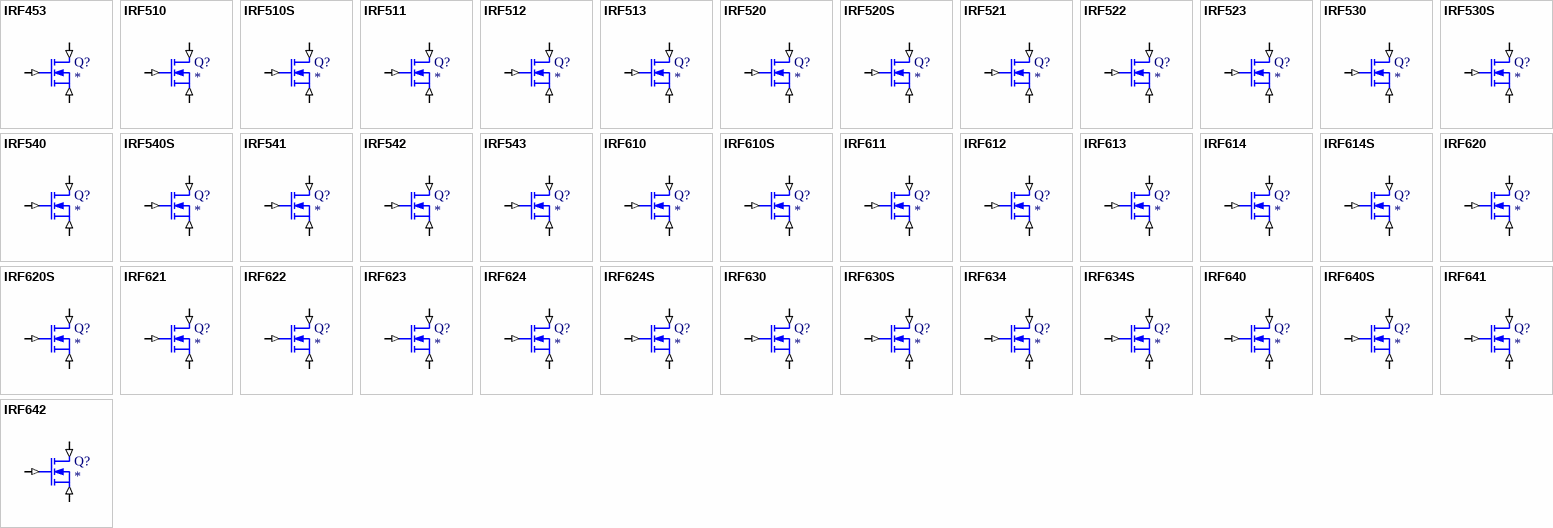
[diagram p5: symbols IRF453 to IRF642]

## IRF453
designator Q?
N-Channel MOSFET
simulation model IRF453 (SUBCKT)
pins: 1 D (in), 2 G (in), 3 S (in)
1 alternate drawing of the same symbol

## IRF510
designator Q?
N-Channel MOSFET
simulation model IRF510 (SUBCKT)
pins: 1 D (in), 2 G (in), 3 S (in)
1 alternate drawing of the same symbol

## IRF510S
designator Q?
N-Channel MOSFET
simulation model IRF510S (SUBCKT)
pins: 1 D (in), 2 G (in), 3 S (in)
1 alternate drawing of the same symbol

## IRF511
designator Q?
N-Channel MOSFET
simulation model IRF511 (SUBCKT)
pins: 1 D (in), 2 G (in), 3 S (in)
1 alternate drawing of the same symbol

## IRF512
designator Q?
N-Channel MOSFET
simulation model IRF512 (SUBCKT)
pins: 1 D (in), 2 G (in), 3 S (in)
1 alternate drawing of the same symbol

## IRF513
designator Q?
N-Channel MOSFET
simulation model IRF513 (SUBCKT)
pins: 1 D (in), 2 G (in), 3 S (in)
1 alternate drawing of the same symbol

## IRF520
designator Q?
N-Channel MOSFET
simulation model IRF520 (SUBCKT)
pins: 1 D (in), 2 G (in), 3 S (in)
1 alternate drawing of the same symbol

## IRF520S
designator Q?
N-Channel MOSFET
simulation model IRF520S (SUBCKT)
pins: 1 D (in), 2 G (in), 3 S (in)
1 alternate drawing of the same symbol

## IRF521
designator Q?
N-Channel MOSFET
simulation model IRF521 (SUBCKT)
pins: 1 D (in), 2 G (in), 3 S (in)
1 alternate drawing of the same symbol

## IRF522
designator Q?
N-Channel MOSFET
simulation model IRF522 (SUBCKT)
pins: 1 D (in), 2 G (in), 3 S (in)
1 alternate drawing of the same symbol

## IRF523
designator Q?
N-Channel MOSFET
simulation model IRF523 (SUBCKT)
pins: 1 D (in), 2 G (in), 3 S (in)
1 alternate drawing of the same symbol

## IRF530
designator Q?
N-Channel MOSFET
simulation model IRF530 (SUBCKT)
pins: 1 D (in), 2 G (in), 3 S (in)
1 alternate drawing of the same symbol

## IRF530S
designator Q?
N-Channel MOSFET
simulation model IRF530S (SUBCKT)
pins: 1 D (in), 2 G (in), 3 S (in)
1 alternate drawing of the same symbol

## IRF540
designator Q?
N-Channel MOSFET
simulation model IRF540 (SUBCKT)
pins: 1 D (in), 2 G (in), 3 S (in)
1 alternate drawing of the same symbol

## IRF540S
designator Q?
N-Channel MOSFET
simulation model IRF540S (SUBCKT)
pins: 1 D (in), 2 G (in), 3 S (in)
1 alternate drawing of the same symbol

## IRF541
designator Q?
N-Channel MOSFET
simulation model IRF541 (SUBCKT)
pins: 1 D (in), 2 G (in), 3 S (in)
1 alternate drawing of the same symbol

## IRF542
designator Q?
N-Channel MOSFET
simulation model IRF542 (SUBCKT)
pins: 1 D (in), 2 G (in), 3 S (in)
1 alternate drawing of the same symbol

## IRF543
designator Q?
N-Channel MOSFET
simulation model IRF543 (SUBCKT)
pins: 1 D (in), 2 G (in), 3 S (in)
1 alternate drawing of the same symbol

## IRF610
designator Q?
N-Channel MOSFET
simulation model IRF610 (SUBCKT)
pins: 1 D (in), 2 G (in), 3 S (in)
1 alternate drawing of the same symbol

## IRF610S
designator Q?
N-Channel MOSFET
simulation model IRF610S (SUBCKT)
pins: 1 D (in), 2 G (in), 3 S (in)
1 alternate drawing of the same symbol

## IRF611
designator Q?
N-Channel MOSFET
simulation model IRF611 (SUBCKT)
pins: 1 D (in), 2 G (in), 3 S (in)
1 alternate drawing of the same symbol

## IRF612
designator Q?
N-Channel MOSFET
simulation model IRF612 (SUBCKT)
pins: 1 D (in), 2 G (in), 3 S (in)
1 alternate drawing of the same symbol

## IRF613
designator Q?
N-Channel MOSFET
simulation model IRF613 (SUBCKT)
pins: 1 D (in), 2 G (in), 3 S (in)
1 alternate drawing of the same symbol

## IRF614
designator Q?
N-Channel MOSFET
simulation model IRF614 (SUBCKT)
pins: 1 D (in), 2 G (in), 3 S (in)
1 alternate drawing of the same symbol

## IRF614S
designator Q?
N-Channel MOSFET
simulation model IRF614S (SUBCKT)
pins: 1 D (in), 2 G (in), 3 S (in)
1 alternate drawing of the same symbol

## IRF620
designator Q?
N-Channel MOSFET
simulation model IRF620 (SUBCKT)
pins: 1 D (in), 2 G (in), 3 S (in)
1 alternate drawing of the same symbol

## IRF620S
designator Q?
N-Channel MOSFET
simulation model IRF620S (SUBCKT)
pins: 1 D (in), 2 G (in), 3 S (in)
1 alternate drawing of the same symbol

## IRF621
designator Q?
N-Channel MOSFET
simulation model IRF621 (SUBCKT)
pins: 1 D (in), 2 G (in), 3 S (in)
1 alternate drawing of the same symbol

## IRF622
designator Q?
N-Channel MOSFET
simulation model IRF622 (SUBCKT)
pins: 1 D (in), 2 G (in), 3 S (in)
1 alternate drawing of the same symbol

## IRF623
designator Q?
N-Channel MOSFET
simulation model IRF623 (SUBCKT)
pins: 1 D (in), 2 G (in), 3 S (in)
1 alternate drawing of the same symbol

## IRF624
designator Q?
N-Channel MOSFET
simulation model IRF624 (SUBCKT)
pins: 1 D (in), 2 G (in), 3 S (in)
1 alternate drawing of the same symbol

## IRF624S
designator Q?
N-Channel MOSFET
simulation model IRF624S (SUBCKT)
pins: 1 D (in), 2 G (in), 3 S (in)
1 alternate drawing of the same symbol

## IRF630
designator Q?
N-Channel MOSFET
simulation model IRF630 (SUBCKT)
pins: 1 D (in), 2 G (in), 3 S (in)
1 alternate drawing of the same symbol

## IRF630S
designator Q?
N-Channel MOSFET
simulation model IRF630S (SUBCKT)
pins: 1 D (in), 2 G (in), 3 S (in)
1 alternate drawing of the same symbol

## IRF634
designator Q?
N-Channel MOSFET
simulation model IRF634 (SUBCKT)
pins: 1 D (in), 2 G (in), 3 S (in)
1 alternate drawing of the same symbol

## IRF634S
designator Q?
N-Channel MOSFET
simulation model IRF634S (SUBCKT)
pins: 1 D (in), 2 G (in), 3 S (in)
1 alternate drawing of the same symbol

## IRF640
designator Q?
N-Channel MOSFET
simulation model IRF640 (SUBCKT)
pins: 1 D (in), 2 G (in), 3 S (in)
1 alternate drawing of the same symbol

## IRF640S
designator Q?
N-Channel MOSFET
simulation model IRF640S (SUBCKT)
pins: 1 D (in), 2 G (in), 3 S (in)
1 alternate drawing of the same symbol

## IRF641
designator Q?
N-Channel MOSFET
simulation model IRF641 (SUBCKT)
pins: 1 D (in), 2 G (in), 3 S (in)
1 alternate drawing of the same symbol

## IRF642
designator Q?
N-Channel MOSFET
simulation model IRF642 (SUBCKT)
pins: 1 D (in), 2 G (in), 3 S (in)
1 alternate drawing of the same symbol

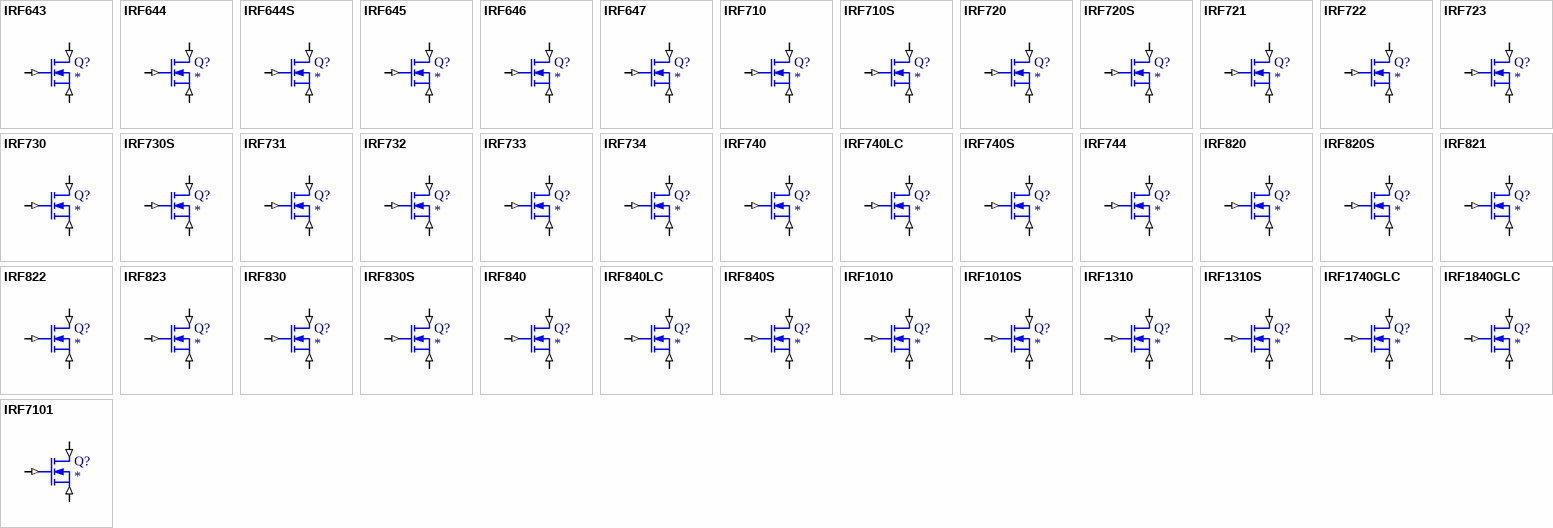
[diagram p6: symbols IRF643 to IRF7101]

## IRF643
designator Q?
N-Channel MOSFET
simulation model IRF643 (SUBCKT)
pins: 1 D (in), 2 G (in), 3 S (in)
1 alternate drawing of the same symbol

## IRF644
designator Q?
N-Channel MOSFET
simulation model IRF644 (SUBCKT)
pins: 1 D (in), 2 G (in), 3 S (in)
1 alternate drawing of the same symbol

## IRF644S
designator Q?
N-Channel MOSFET
simulation model IRF644S (SUBCKT)
pins: 1 D (in), 2 G (in), 3 S (in)
1 alternate drawing of the same symbol

## IRF645
designator Q?
N-Channel MOSFET
simulation model IRF645 (SUBCKT)
pins: 1 D (in), 2 G (in), 3 S (in)
1 alternate drawing of the same symbol

## IRF646
designator Q?
N-Channel MOSFET
simulation model IRF646 (SUBCKT)
pins: 1 D (in), 2 G (in), 3 S (in)
1 alternate drawing of the same symbol

## IRF647
designator Q?
N-Channel MOSFET
simulation model IRF647 (SUBCKT)
pins: 1 D (in), 2 G (in), 3 S (in)
1 alternate drawing of the same symbol

## IRF710
designator Q?
N-Channel MOSFET
simulation model IRF710 (SUBCKT)
pins: 1 D (in), 2 G (in), 3 S (in)
1 alternate drawing of the same symbol

## IRF710S
designator Q?
N-Channel MOSFET
simulation model IRF710S (SUBCKT)
pins: 1 D (in), 2 G (in), 3 S (in)
1 alternate drawing of the same symbol

## IRF720
designator Q?
N-Channel MOSFET
simulation model IRF720 (SUBCKT)
pins: 1 D (in), 2 G (in), 3 S (in)
1 alternate drawing of the same symbol

## IRF720S
designator Q?
N-Channel MOSFET
simulation model IRF720S (SUBCKT)
pins: 1 D (in), 2 G (in), 3 S (in)
1 alternate drawing of the same symbol

## IRF721
designator Q?
N-Channel MOSFET
simulation model IRF721 (SUBCKT)
pins: 1 D (in), 2 G (in), 3 S (in)
1 alternate drawing of the same symbol

## IRF722
designator Q?
N-Channel MOSFET
simulation model IRF722 (SUBCKT)
pins: 1 D (in), 2 G (in), 3 S (in)
1 alternate drawing of the same symbol

## IRF723
designator Q?
N-Channel MOSFET
simulation model IRF723 (SUBCKT)
pins: 1 D (in), 2 G (in), 3 S (in)
1 alternate drawing of the same symbol

## IRF730
designator Q?
N-Channel MOSFET
simulation model IRF730 (SUBCKT)
pins: 1 D (in), 2 G (in), 3 S (in)
1 alternate drawing of the same symbol

## IRF730S
designator Q?
N-Channel MOSFET
simulation model IRF730S (SUBCKT)
pins: 1 D (in), 2 G (in), 3 S (in)
1 alternate drawing of the same symbol

## IRF731
designator Q?
N-Channel MOSFET
simulation model IRF731 (SUBCKT)
pins: 1 D (in), 2 G (in), 3 S (in)
1 alternate drawing of the same symbol

## IRF732
designator Q?
N-Channel MOSFET
simulation model IRF732 (SUBCKT)
pins: 1 D (in), 2 G (in), 3 S (in)
1 alternate drawing of the same symbol

## IRF733
designator Q?
N-Channel MOSFET
simulation model IRF733 (SUBCKT)
pins: 1 D (in), 2 G (in), 3 S (in)
1 alternate drawing of the same symbol

## IRF734
designator Q?
N-Channel MOSFET
simulation model IRF734 (SUBCKT)
pins: 1 D (in), 2 G (in), 3 S (in)
1 alternate drawing of the same symbol

## IRF740
designator Q?
N-Channel MOSFET
simulation model IRF740 (SUBCKT)
pins: 1 D (in), 2 G (in), 3 S (in)
1 alternate drawing of the same symbol

## IRF740LC
designator Q?
N-Channel MOSFET
simulation model IRF740LC (SUBCKT)
pins: 1 D (in), 2 G (in), 3 S (in)
1 alternate drawing of the same symbol

## IRF740S
designator Q?
N-Channel MOSFET
simulation model IRF740S (SUBCKT)
pins: 1 D (in), 2 G (in), 3 S (in)
1 alternate drawing of the same symbol

## IRF744
designator Q?
N-Channel MOSFET
simulation model IRF744 (SUBCKT)
pins: 1 D (in), 2 G (in), 3 S (in)
1 alternate drawing of the same symbol

## IRF820
designator Q?
N-Channel MOSFET
simulation model IRF820 (SUBCKT)
pins: 1 D (in), 2 G (in), 3 S (in)
1 alternate drawing of the same symbol

## IRF820S
designator Q?
N-Channel MOSFET
simulation model IRF820S (SUBCKT)
pins: 1 D (in), 2 G (in), 3 S (in)
1 alternate drawing of the same symbol

## IRF821
designator Q?
N-Channel MOSFET
simulation model IRF821 (SUBCKT)
pins: 1 D (in), 2 G (in), 3 S (in)
1 alternate drawing of the same symbol

## IRF822
designator Q?
N-Channel MOSFET
simulation model IRF822 (SUBCKT)
pins: 1 D (in), 2 G (in), 3 S (in)
1 alternate drawing of the same symbol

## IRF823
designator Q?
N-Channel MOSFET
simulation model IRF823 (SUBCKT)
pins: 1 D (in), 2 G (in), 3 S (in)
1 alternate drawing of the same symbol

## IRF830
designator Q?
N-Channel MOSFET
simulation model IRF830 (SUBCKT)
pins: 1 D (in), 2 G (in), 3 S (in)
1 alternate drawing of the same symbol

## IRF830S
designator Q?
N-Channel MOSFET
simulation model IRF830S (SUBCKT)
pins: 1 D (in), 2 G (in), 3 S (in)
1 alternate drawing of the same symbol

## IRF840
designator Q?
N-Channel MOSFET
simulation model IRF840 (SUBCKT)
pins: 1 D (in), 2 G (in), 3 S (in)
1 alternate drawing of the same symbol

## IRF840LC
designator Q?
N-Channel MOSFET
simulation model IRF840LC (SUBCKT)
pins: 1 D (in), 2 G (in), 3 S (in)
1 alternate drawing of the same symbol

## IRF840S
designator Q?
N-Channel MOSFET
simulation model IRF840S (SUBCKT)
pins: 1 D (in), 2 G (in), 3 S (in)
1 alternate drawing of the same symbol

## IRF1010
designator Q?
N-Channel MOSFET
simulation model IRF1010 (SUBCKT)
pins: 1 D (in), 2 G (in), 3 S (in)
1 alternate drawing of the same symbol

## IRF1010S
designator Q?
N-Channel MOSFET
simulation model IRF1010S (SUBCKT)
pins: 1 D (in), 2 G (in), 3 S (in)
1 alternate drawing of the same symbol

## IRF1310
designator Q?
N-Channel MOSFET
simulation model IRF1310 (SUBCKT)
pins: 1 D (in), 2 G (in), 3 S (in)
1 alternate drawing of the same symbol

## IRF1310S
designator Q?
N-Channel MOSFET
simulation model IRF1310S (SUBCKT)
pins: 1 D (in), 2 G (in), 3 S (in)
1 alternate drawing of the same symbol

## IRF1740GLC
designator Q?
N-Channel MOSFET
simulation model IRF1740GLC (SUBCKT)
pins: 1 D (in), 2 G (in), 3 S (in)
1 alternate drawing of the same symbol

## IRF1840GLC
designator Q?
N-Channel MOSFET
simulation model IRF1840GLC (SUBCKT)
pins: 1 D (in), 2 G (in), 3 S (in)
1 alternate drawing of the same symbol

## IRF7101
designator Q?
N-Channel MOSFET
simulation model IRF7101 (SUBCKT)
pins: 1 D (in), 2 G (in), 3 S (in)
1 alternate drawing of the same symbol

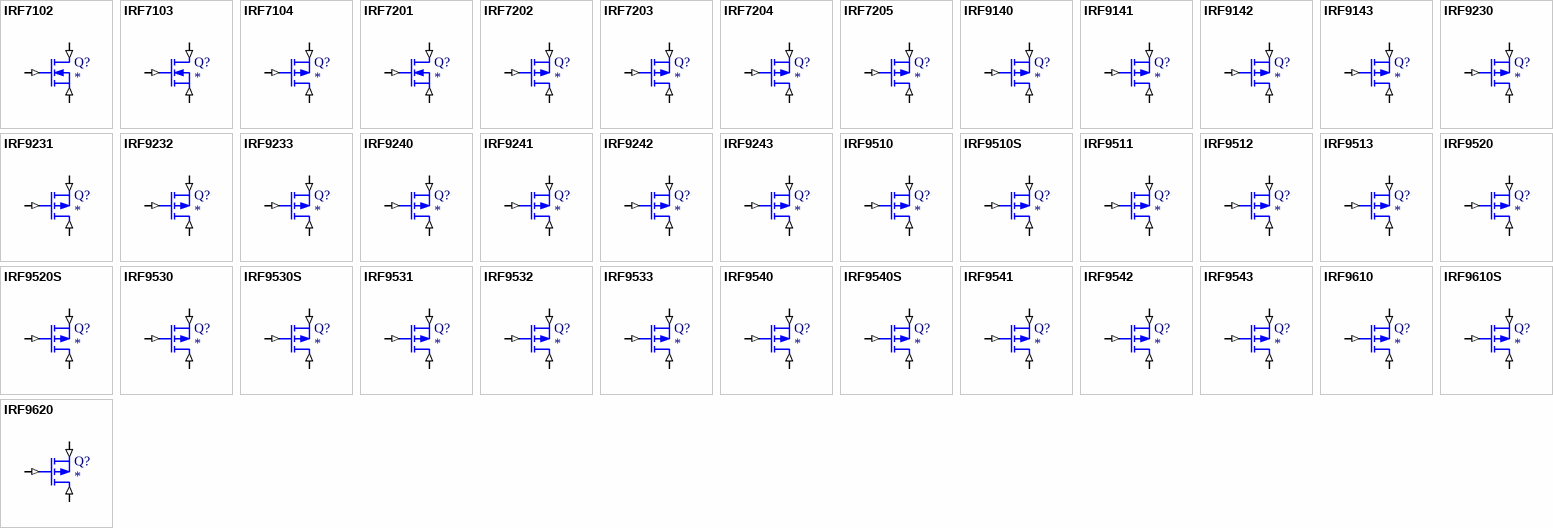
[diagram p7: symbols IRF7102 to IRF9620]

## IRF7102
designator Q?
N-Channel MOSFET
simulation model IRF7102 (SUBCKT)
pins: 1 D (in), 2 G (in), 3 S (in)
1 alternate drawing of the same symbol

## IRF7103
designator Q?
N-Channel MOSFET
simulation model IRF7103 (SUBCKT)
pins: 1 D (in), 2 G (in), 3 S (in)
1 alternate drawing of the same symbol

## IRF7104
designator Q?
P-Channel MOSFET
simulation model IRF7104 (SUBCKT)
pins: 1 D (in), 2 G (in), 3 S (in)
1 alternate drawing of the same symbol

## IRF7201
designator Q?
N-Channel MOSFET
simulation model IRF7201 (SUBCKT)
pins: 1 D (in), 2 G (in), 3 S (in)
1 alternate drawing of the same symbol

## IRF7202
designator Q?
P-Channel MOSFET
simulation model IRF7202 (SUBCKT)
pins: 1 D (in), 2 G (in), 3 S (in)
1 alternate drawing of the same symbol

## IRF7203
designator Q?
P-Channel MOSFET
simulation model IRF7203 (SUBCKT)
pins: 1 D (in), 2 G (in), 3 S (in)
1 alternate drawing of the same symbol

## IRF7204
designator Q?
P-Channel MOSFET
simulation model IRF7204 (SUBCKT)
pins: 1 D (in), 2 G (in), 3 S (in)
1 alternate drawing of the same symbol

## IRF7205
designator Q?
P-Channel MOSFET
simulation model IRF7205 (SUBCKT)
pins: 1 D (in), 2 G (in), 3 S (in)
1 alternate drawing of the same symbol

## IRF9140
designator Q?
P-Channel MOSFET
simulation model IRF9140 (SUBCKT)
pins: 1 D (in), 2 G (in), 3 S (in)
1 alternate drawing of the same symbol

## IRF9141
designator Q?
P-Channel MOSFET
simulation model IRF9141 (SUBCKT)
pins: 1 D (in), 2 G (in), 3 S (in)
1 alternate drawing of the same symbol

## IRF9142
designator Q?
P-Channel MOSFET
simulation model IRF9142 (SUBCKT)
pins: 1 D (in), 2 G (in), 3 S (in)
1 alternate drawing of the same symbol

## IRF9143
designator Q?
P-Channel MOSFET
simulation model IRF9143 (SUBCKT)
pins: 1 D (in), 2 G (in), 3 S (in)
1 alternate drawing of the same symbol

## IRF9230
designator Q?
P-Channel MOSFET
simulation model IRF9230 (SUBCKT)
pins: 1 D (in), 2 G (in), 3 S (in)
1 alternate drawing of the same symbol

## IRF9231
designator Q?
P-Channel MOSFET
simulation model IRF9231 (SUBCKT)
pins: 1 D (in), 2 G (in), 3 S (in)
1 alternate drawing of the same symbol

## IRF9232
designator Q?
P-Channel MOSFET
simulation model IRF9232 (SUBCKT)
pins: 1 D (in), 2 G (in), 3 S (in)
1 alternate drawing of the same symbol

## IRF9233
designator Q?
P-Channel MOSFET
simulation model IRF9233 (SUBCKT)
pins: 1 D (in), 2 G (in), 3 S (in)
1 alternate drawing of the same symbol

## IRF9240
designator Q?
P-Channel MOSFET
simulation model IRF9240 (SUBCKT)
pins: 1 D (in), 2 G (in), 3 S (in)
1 alternate drawing of the same symbol

## IRF9241
designator Q?
P-Channel MOSFET
simulation model IRF9241 (SUBCKT)
pins: 1 D (in), 2 G (in), 3 S (in)
1 alternate drawing of the same symbol

## IRF9242
designator Q?
P-Channel MOSFET
simulation model IRF9242 (SUBCKT)
pins: 1 D (in), 2 G (in), 3 S (in)
1 alternate drawing of the same symbol

## IRF9243
designator Q?
P-Channel MOSFET
simulation model IRF9243 (SUBCKT)
pins: 1 D (in), 2 G (in), 3 S (in)
1 alternate drawing of the same symbol

## IRF9510
designator Q?
P-Channel MOSFET
simulation model IRF9510 (SUBCKT)
pins: 1 D (in), 2 G (in), 3 S (in)
1 alternate drawing of the same symbol

## IRF9510S
designator Q?
P-Channel MOSFET
simulation model IRF9510S (SUBCKT)
pins: 1 D (in), 2 G (in), 3 S (in)
1 alternate drawing of the same symbol

## IRF9511
designator Q?
P-Channel MOSFET
simulation model IRF9511 (SUBCKT)
pins: 1 D (in), 2 G (in), 3 S (in)
1 alternate drawing of the same symbol

## IRF9512
designator Q?
P-Channel MOSFET
simulation model IRF9512 (SUBCKT)
pins: 1 D (in), 2 G (in), 3 S (in)
1 alternate drawing of the same symbol

## IRF9513
designator Q?
P-Channel MOSFET
simulation model IRF9513 (SUBCKT)
pins: 1 D (in), 2 G (in), 3 S (in)
1 alternate drawing of the same symbol

## IRF9520
designator Q?
P-Channel MOSFET
simulation model IRF9520 (SUBCKT)
pins: 1 D (in), 2 G (in), 3 S (in)
1 alternate drawing of the same symbol

## IRF9520S
designator Q?
P-Channel MOSFET
simulation model IRF9520S (SUBCKT)
pins: 1 D (in), 2 G (in), 3 S (in)
1 alternate drawing of the same symbol

## IRF9530
designator Q?
P-Channel MOSFET
simulation model IRF9530 (SUBCKT)
pins: 1 D (in), 2 G (in), 3 S (in)
1 alternate drawing of the same symbol

## IRF9530S
designator Q?
P-Channel MOSFET
simulation model IRF9530S (SUBCKT)
pins: 1 D (in), 2 G (in), 3 S (in)
1 alternate drawing of the same symbol

## IRF9531
designator Q?
P-Channel MOSFET
simulation model IRF9531 (SUBCKT)
pins: 1 D (in), 2 G (in), 3 S (in)
1 alternate drawing of the same symbol

## IRF9532
designator Q?
P-Channel MOSFET
simulation model IRF9532 (SUBCKT)
pins: 1 D (in), 2 G (in), 3 S (in)
1 alternate drawing of the same symbol

## IRF9533
designator Q?
P-Channel MOSFET
simulation model IRF9533 (SUBCKT)
pins: 1 D (in), 2 G (in), 3 S (in)
1 alternate drawing of the same symbol

## IRF9540
designator Q?
P-Channel MOSFET
simulation model IRF9540 (SUBCKT)
pins: 1 D (in), 2 G (in), 3 S (in)
1 alternate drawing of the same symbol

## IRF9540S
designator Q?
P-Channel MOSFET
simulation model IRF9540S (SUBCKT)
pins: 1 D (in), 2 G (in), 3 S (in)
1 alternate drawing of the same symbol

## IRF9541
designator Q?
P-Channel MOSFET
simulation model IRF9541 (SUBCKT)
pins: 1 D (in), 2 G (in), 3 S (in)
1 alternate drawing of the same symbol

## IRF9542
designator Q?
P-Channel MOSFET
simulation model IRF9542 (SUBCKT)
pins: 1 D (in), 2 G (in), 3 S (in)
1 alternate drawing of the same symbol

## IRF9543
designator Q?
P-Channel MOSFET
simulation model IRF9543 (SUBCKT)
pins: 1 D (in), 2 G (in), 3 S (in)
1 alternate drawing of the same symbol

## IRF9610
designator Q?
P-Channel MOSFET
simulation model IRF9610 (SUBCKT)
pins: 1 D (in), 2 G (in), 3 S (in)
1 alternate drawing of the same symbol

## IRF9610S
designator Q?
P-Channel MOSFET
simulation model IRF9610S (SUBCKT)
pins: 1 D (in), 2 G (in), 3 S (in)
1 alternate drawing of the same symbol

## IRF9620
designator Q?
P-Channel MOSFET
simulation model IRF9620 (SUBCKT)
pins: 1 D (in), 2 G (in), 3 S (in)
1 alternate drawing of the same symbol

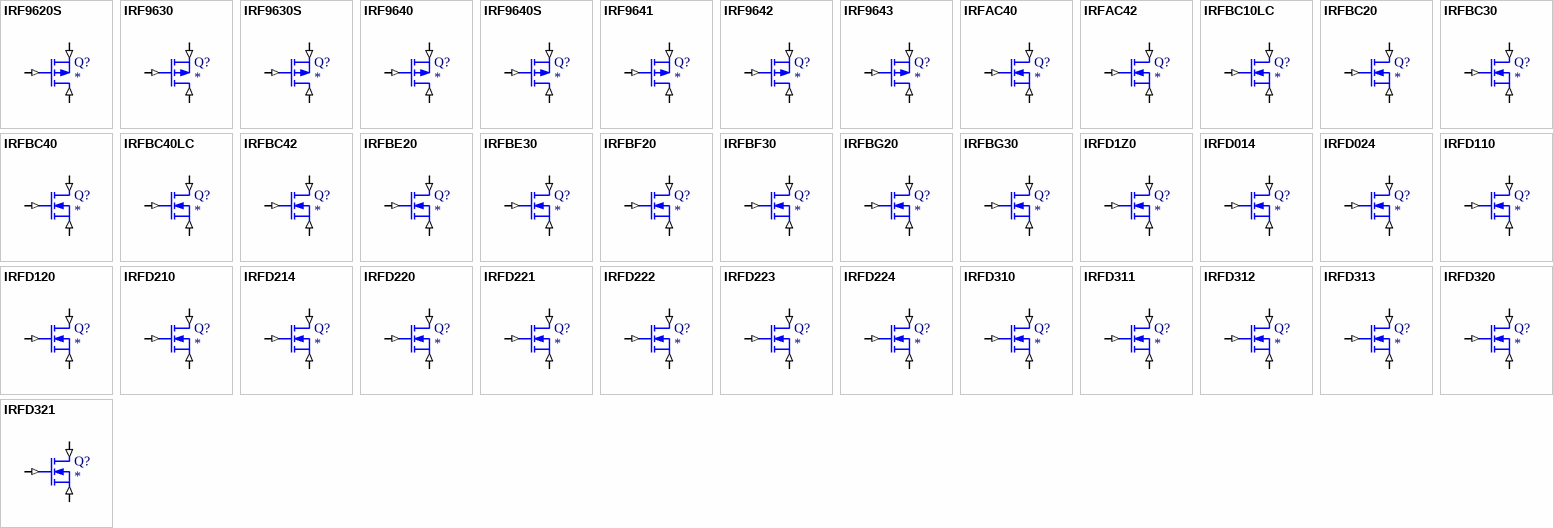
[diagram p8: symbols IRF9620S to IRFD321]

## IRF9620S
designator Q?
P-Channel MOSFET
simulation model IRF9620S (SUBCKT)
pins: 1 D (in), 2 G (in), 3 S (in)
1 alternate drawing of the same symbol

## IRF9630
designator Q?
P-Channel MOSFET
simulation model IRF9630 (SUBCKT)
pins: 1 D (in), 2 G (in), 3 S (in)
1 alternate drawing of the same symbol

## IRF9630S
designator Q?
P-Channel MOSFET
simulation model IRF9630S (SUBCKT)
pins: 1 D (in), 2 G (in), 3 S (in)
1 alternate drawing of the same symbol

## IRF9640
designator Q?
P-Channel MOSFET
simulation model IRF9640 (SUBCKT)
pins: 1 D (in), 2 G (in), 3 S (in)
1 alternate drawing of the same symbol

## IRF9640S
designator Q?
P-Channel MOSFET
simulation model IRF9640S (SUBCKT)
pins: 1 D (in), 2 G (in), 3 S (in)
1 alternate drawing of the same symbol

## IRF9641
designator Q?
P-Channel MOSFET
simulation model IRF9641 (SUBCKT)
pins: 1 D (in), 2 G (in), 3 S (in)
1 alternate drawing of the same symbol

## IRF9642
designator Q?
P-Channel MOSFET
simulation model IRF9642 (SUBCKT)
pins: 1 D (in), 2 G (in), 3 S (in)
1 alternate drawing of the same symbol

## IRF9643
designator Q?
P-Channel MOSFET
simulation model IRF9643 (SUBCKT)
pins: 1 D (in), 2 G (in), 3 S (in)
1 alternate drawing of the same symbol

## IRFAC40
designator Q?
N-Channel MOSFET
simulation model IRFAC40 (SUBCKT)
pins: 1 D (in), 2 G (in), 3 S (in)
1 alternate drawing of the same symbol

## IRFAC42
designator Q?
N-Channel MOSFET
simulation model IRFAC42 (SUBCKT)
pins: 1 D (in), 2 G (in), 3 S (in)
1 alternate drawing of the same symbol

## IRFBC10LC
designator Q?
N-Channel MOSFET
simulation model IRFBC10LC (SUBCKT)
pins: 1 D (in), 2 G (in), 3 S (in)
1 alternate drawing of the same symbol

## IRFBC20
designator Q?
N-Channel MOSFET
simulation model IRFBC20 (SUBCKT)
pins: 1 D (in), 2 G (in), 3 S (in)
1 alternate drawing of the same symbol

## IRFBC30
designator Q?
N-Channel MOSFET
simulation model IRFBC30 (SUBCKT)
pins: 1 D (in), 2 G (in), 3 S (in)
1 alternate drawing of the same symbol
